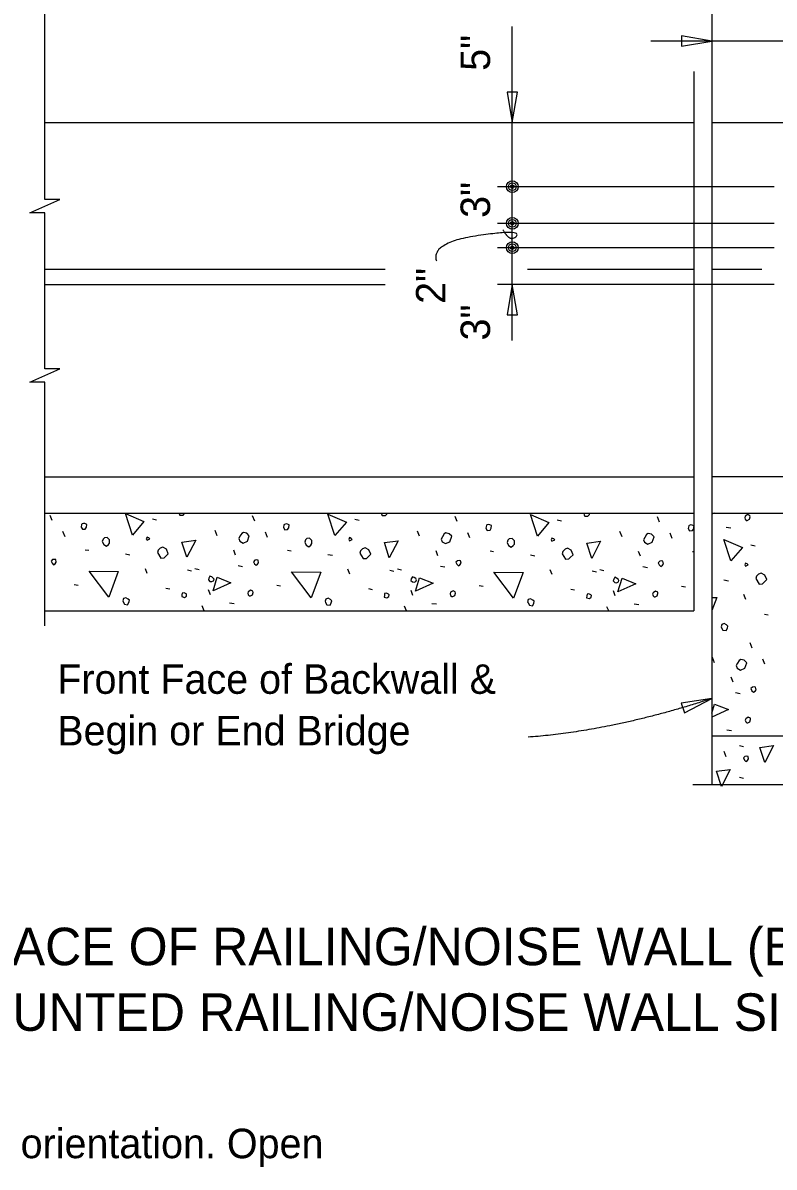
# Model space of a CAD drawing. Extents: x 120631.6 to 120706.2, y 120663.5 to 120716.4.
# Drawn here: x 120645.66 to 120650.79, y 120690.08 to 120697.89 of the extents above; entities that cross this region are included whole.
import ezdxf

# ---------------------------------------------------------------- set-up
doc = ezdxf.new("R2010")
doc.units = 0
for name, color, linetype in [('Dimension', 7, 'Continuous'), ('Miscellaneous', 7, 'Continuous'), ('TextStructures', 7, 'Continuous'), ('TrafBarrierConc', 7, 'Continuous')]:
    doc.layers.add(name, color=color, linetype=linetype)

msp = doc.modelspace()

# ---------------------------------------------------------------- linework, layer by layer
at = {"layer": 'Dimension'}
for p, q in [((120648.9987, 120695.7265), (120648.9987, 120697.8695)), ((120652.0739, 120697.7695), (120649.9443, 120697.7695)), ((120650.787, 120696.7752), (120648.8978, 120696.7752)), ((120650.787, 120696.5252), (120648.8978, 120696.5252)), ((120650.787, 120696.3586), (120648.8978, 120696.3586)), ((120650.787, 120696.1086), (120648.8978, 120696.1086))]:
    msp.add_line(p, q, dxfattribs=at)
for points in [[(120645.8063, 120697.2127), (120645.8063, 120699.4757), (120645.703, 120699.4757), (120645.8063, 120699.5207), (120645.9097, 120699.5657), (120645.8063, 120699.5657), (120645.8063, 120702.646)], [(120645.8063, 120696.2127), (120645.8063, 120696.597), (120645.703, 120696.597), (120645.8063, 120696.642), (120645.9097, 120696.687), (120645.8063, 120696.687), (120645.8063, 120697.2127)], [(120645.8063, 120693.7786), (120645.8063, 120695.4418), (120645.703, 120695.4418), (120645.8063, 120695.4868), (120645.9097, 120695.5318), (120645.8063, 120695.5318), (120645.8063, 120696.2127)], [(120651.6828, 120692.6914), (120650.9858, 120692.6914), (120650.9858, 120692.5751), (120650.8864, 120692.8001), (120650.8864, 120692.6914), (120650.2312, 120692.6914)]]:
    msp.add_lwpolyline(points, dxfattribs=at)
for points in [[(120650.362, 120697.7695), (120650.1537, 120697.8048), (120650.1537, 120697.7342)], [(120648.9987, 120697.2127), (120649.0339, 120697.421), (120648.9634, 120697.421)], [(120648.9987, 120696.1086), (120648.9634, 120695.9003), (120649.0339, 120695.9003)], [(120650.362, 120693.2821), (120650.1532, 120693.2502), (120650.1754, 120693.1832)]]:
    msp.add_lwpolyline(points, close=True, dxfattribs=at)
for centre, radius in [((120648.9994, 120696.7756), 0.0399), ((120648.9994, 120696.7756), 0.0262), ((120648.9994, 120696.7756), 0.0118), ((120648.9994, 120696.5256), 0.0399), ((120648.9994, 120696.5256), 0.0262), ((120648.9994, 120696.5256), 0.0118), ((120648.9994, 120696.3589), 0.0399), ((120648.9994, 120696.3589), 0.0262), ((120648.9994, 120696.3589), 0.0118)]:
    msp.add_circle(centre, radius, dxfattribs=at)
for points in [[(120648.9344, 120696.4819), (120648.9857, 120696.39), (120649.069, 120696.4866), (120648.4422, 120696.3928), (120648.4805, 120696.2684)], [(120650.362, 120693.2821), (120649.6982, 120693.0626), (120649.1068, 120693.0177)]]:
    msp.add_open_spline(points, degree=2, dxfattribs=at)
at = {"layer": 'Miscellaneous'}
for p, q in [((120645.8575, 120694.4966), (120645.8434, 120694.5319)), ((120646.5416, 120694.509), (120646.5699, 120694.5019)), ((120647.2399, 120694.4931), (120647.2257, 120694.5284)), ((120647.924, 120694.5054), (120647.9523, 120694.4983)), ((120648.6223, 120694.4895), (120648.6081, 120694.5249)), ((120649.3064, 120694.5019), (120649.3347, 120694.4949)), ((120650.0047, 120694.486), (120649.9905, 120694.5214)), ((120645.9441, 120694.3852), (120645.93, 120694.4206)), ((120646.9836, 120694.3923), (120646.9694, 120694.4277)), ((120647.3265, 120694.3817), (120647.3124, 120694.417)), ((120648.366, 120694.3888), (120648.3518, 120694.4241)), ((120648.7089, 120694.3781), (120648.6948, 120694.4135)), ((120649.7484, 120694.3852), (120649.7342, 120694.4206)), ((120650.0913, 120694.3746), (120650.0772, 120694.41)), ((120650.4607, 120694.4502), (120650.4926, 120694.4466)), ((120646.082, 120694.2968), (120646.1067, 120694.2933)), ((120650.6287, 120694.3317), (120650.657, 120694.3247)), ((120646.3578, 120694.2686), (120646.3878, 120694.2632)), ((120647.1091, 120694.2597), (120647.0967, 120694.2933)), ((120647.4644, 120694.2933), (120647.4891, 120694.2897)), ((120647.7402, 120694.265), (120647.7702, 120694.2597)), ((120648.4915, 120694.2562), (120648.4791, 120694.2897)), ((120648.8468, 120694.2897), (120648.8715, 120694.2863)), ((120649.1226, 120694.2615), (120649.1526, 120694.2562)), ((120649.8739, 120694.2527), (120649.8615, 120694.2863)), ((120650.2292, 120694.2863), (120650.2395, 120694.2848)), ((120646.5063, 120694.1342), (120646.4939, 120694.1678)), ((120646.7803, 120694.1607), (120646.8086, 120694.1537)), ((120646.8315, 120694.1695), (120646.8598, 120694.1625)), ((120647.1267, 120694.189), (120647.1568, 120694.1837)), ((120647.8887, 120694.1307), (120647.8763, 120694.1643)), ((120648.1627, 120694.1572), (120648.191, 120694.1501)), ((120648.2139, 120694.1661), (120648.2422, 120694.159)), ((120648.5091, 120694.1855), (120648.5392, 120694.1802)), ((120649.2711, 120694.1271), (120649.2587, 120694.1607)), ((120649.5451, 120694.1537), (120649.5734, 120694.1466)), ((120649.5963, 120694.1625), (120649.6246, 120694.1554)), ((120649.8915, 120694.1819), (120649.9216, 120694.1766)), ((120650.4448, 120694.0913), (120650.4749, 120694.086)), ((120646.0078, 120694.06), (120646.0343, 120694.0546)), ((120646.6336, 120694.0352), (120646.6601, 120694.0299)), ((120646.9376, 120693.9892), (120646.9252, 120694.0228)), ((120647.3902, 120694.0564), (120647.4167, 120694.0511)), ((120648.016, 120694.0317), (120648.0425, 120694.0264)), ((120648.32, 120693.9857), (120648.3076, 120694.0193)), ((120648.7726, 120694.0529), (120648.7991, 120694.0476)), ((120649.3984, 120694.0281), (120649.4249, 120694.0228)), ((120649.7024, 120693.9822), (120649.69, 120694.0158)), ((120650.155, 120694.0493), (120650.1815, 120694.0441)), ((120650.5933, 120693.957), (120650.5809, 120693.9906)), ((120646.8952, 120693.8796), (120646.8811, 120693.915)), ((120647.0666, 120693.9344), (120647.0985, 120693.9309)), ((120648.2763, 120693.8794), (120648.2635, 120693.9115)), ((120648.449, 120693.9309), (120648.4809, 120693.9274)), ((120649.6573, 120693.8794), (120649.6459, 120693.9079)), ((120649.8314, 120693.9274), (120649.8632, 120693.9239)), ((120650.7206, 120693.858), (120650.7471, 120693.8527)), ((120650.6375, 120693.6264), (120650.6234, 120693.6618)), ((120650.3812, 120693.5256), (120650.367, 120693.561)), ((120650.7241, 120693.515), (120650.71, 120693.5504)), ((120650.5067, 120693.3931), (120650.4943, 120693.4266)), ((120650.5244, 120693.3223), (120650.5544, 120693.317)), ((120650.4643, 120693.0678), (120650.4961, 120693.0643)), ((120650.4601, 120692.8837), (120650.446, 120692.919)), ((120650.5506, 120692.9603), (120650.5771, 120692.955)), ((120650.5506, 120692.7437), (120650.5771, 120692.7384))]:
    msp.add_line(p, q, dxfattribs=at)
for points in [[(120646.4055, 120694.3976), (120646.3578, 120694.5443), (120646.4833, 120694.4895), (120646.4055, 120694.3976)], [(120646.7237, 120694.5461), (120646.729, 120694.5337), (120646.7255, 120694.5372)], [(120646.729, 120694.5337), (120646.7502, 120694.5337), (120646.7609, 120694.5443), (120646.7604, 120694.5461)], [(120647.7879, 120694.3941), (120647.7402, 120694.5408), (120647.8657, 120694.486), (120647.7879, 120694.3941)], [(120648.1082, 120694.5461), (120648.1061, 120694.5426), (120648.1114, 120694.5302), (120648.1079, 120694.5337)], [(120648.1114, 120694.5302), (120648.1326, 120694.5302), (120648.1432, 120694.5408), (120648.1418, 120694.5461)], [(120649.1703, 120694.3905), (120649.1226, 120694.5372), (120649.2481, 120694.4825), (120649.1703, 120694.3905)], [(120649.4927, 120694.5461), (120649.4885, 120694.539), (120649.4938, 120694.5267), (120649.4903, 120694.5302)], [(120649.4938, 120694.5267), (120649.515, 120694.5267), (120649.5256, 120694.5372), (120649.5232, 120694.5461)], [(120650.3777, 120694.546), (120650.362, 120694.5389)], [(120650.5969, 120694.4979), (120650.6039, 120694.4979), (120650.6181, 120694.505), (120650.6234, 120694.5209), (120650.6216, 120694.5297), (120650.6075, 120694.5368), (120650.5898, 120694.5262), (120650.5862, 120694.5156), (120650.5898, 120694.505), (120650.5969, 120694.4979)], [(120646.0537, 120694.4524), (120646.0626, 120694.4365), (120646.082, 120694.4382), (120646.0909, 120694.4506), (120646.0926, 120694.4701), (120646.0802, 120694.4754), (120646.0714, 120694.4771), (120646.0608, 120694.4736), (120646.0573, 120694.4701), (120646.0537, 120694.4524)], [(120647.4361, 120694.4489), (120647.445, 120694.433), (120647.4644, 120694.4347), (120647.4732, 120694.4471), (120647.475, 120694.4666), (120647.4626, 120694.4718), (120647.4538, 120694.4736), (120647.4432, 120694.4701), (120647.4397, 120694.4666), (120647.4361, 120694.4489)], [(120648.8185, 120694.4453), (120648.8274, 120694.4294), (120648.8468, 120694.4312), (120648.8556, 120694.4436), (120648.8574, 120694.463), (120648.845, 120694.4683), (120648.8362, 120694.4701), (120648.8256, 120694.4666), (120648.8221, 120694.463), (120648.8185, 120694.4453)], [(120650.2395, 120694.4596), (120650.2274, 120694.4648), (120650.2186, 120694.4666), (120650.208, 120694.463), (120650.2044, 120694.4595), (120650.2009, 120694.4418)], [(120650.2009, 120694.4418), (120650.2098, 120694.4259), (120650.2292, 120694.4277), (120650.238, 120694.44), (120650.2395, 120694.4561)], [(120646.1987, 120694.3534), (120646.2093, 120694.3322), (120646.2269, 120694.3216), (120646.2411, 120694.3322), (120646.2482, 120694.3428), (120646.2482, 120694.364), (120646.2323, 120694.3799), (120646.2128, 120694.3781), (120646.204, 120694.3693), (120646.1987, 120694.3534)], [(120646.5045, 120694.3622), (120646.524, 120694.3711), (120646.5169, 120694.3781), (120646.5045, 120694.3834), (120646.4992, 120694.3711), (120646.5045, 120694.3622)], [(120647.1374, 120694.3552), (120647.1603, 120694.3428), (120647.1904, 120694.3552), (120647.2028, 120694.3923), (120647.1851, 120694.41), (120647.1621, 120694.4153), (120647.1515, 120694.4082), (120647.1391, 120694.3888), (120647.1303, 120694.3729), (120647.1374, 120694.3552)], [(120647.5811, 120694.3499), (120647.5917, 120694.3287), (120647.6093, 120694.318), (120647.6235, 120694.3287), (120647.6306, 120694.3393), (120647.6306, 120694.3605), (120647.6147, 120694.3764), (120647.5952, 120694.3746), (120647.5864, 120694.3658), (120647.5811, 120694.3499)], [(120647.8869, 120694.3587), (120647.9063, 120694.3676), (120647.8993, 120694.3746), (120647.8869, 120694.3799), (120647.8816, 120694.3676), (120647.8869, 120694.3587)], [(120648.5198, 120694.3516), (120648.5427, 120694.3393), (120648.5728, 120694.3516), (120648.5852, 120694.3888), (120648.5675, 120694.4065), (120648.5445, 120694.4117), (120648.5339, 120694.4047), (120648.5215, 120694.3852), (120648.5127, 120694.3693), (120648.5198, 120694.3516)], [(120648.9635, 120694.3464), (120648.9741, 120694.3251), (120648.9917, 120694.3145), (120649.0059, 120694.3251), (120649.013, 120694.3357), (120649.013, 120694.3569), (120648.9971, 120694.3729), (120648.9776, 120694.3711), (120648.9688, 120694.3622), (120648.9635, 120694.3464)], [(120649.2693, 120694.3552), (120649.2887, 120694.364), (120649.2817, 120694.3711), (120649.2693, 120694.3764), (120649.264, 120694.364), (120649.2693, 120694.3552)], [(120649.9022, 120694.3481), (120649.9251, 120694.3357), (120649.9552, 120694.3481), (120649.9676, 120694.3852), (120649.9499, 120694.4029), (120649.9269, 120694.4082), (120649.9163, 120694.4012), (120649.9039, 120694.3817), (120649.8951, 120694.3658), (120649.9022, 120694.3481)], [(120646.5752, 120694.2774), (120646.5982, 120694.2403), (120646.6212, 120694.242), (120646.63, 120694.2509), (120646.6494, 120694.2703), (120646.6371, 120694.3004), (120646.6124, 120694.3145), (120646.5947, 120694.3075), (120646.5805, 120694.2933), (120646.5752, 120694.2774)], [(120646.7767, 120694.2456), (120646.7431, 120694.3499), (120646.8368, 120694.3622), (120646.7767, 120694.2456)], [(120647.9576, 120694.2739), (120647.9806, 120694.2367), (120648.0036, 120694.2385), (120648.0124, 120694.2474), (120648.0318, 120694.2668), (120648.0195, 120694.2968), (120647.9948, 120694.311), (120647.9771, 120694.3039), (120647.9629, 120694.2897), (120647.9576, 120694.2739)], [(120648.1591, 120694.242), (120648.1255, 120694.3464), (120648.2192, 120694.3587), (120648.1591, 120694.242)], [(120649.34, 120694.2703), (120649.363, 120694.2332), (120649.386, 120694.235), (120649.3948, 120694.2438), (120649.4142, 120694.2632), (120649.4019, 120694.2933), (120649.3771, 120694.3075), (120649.3594, 120694.3004), (120649.3453, 120694.2863), (120649.34, 120694.2703)], [(120649.5415, 120694.2385), (120649.5079, 120694.3428), (120649.6016, 120694.3552), (120649.5415, 120694.2385)], [(120650.4926, 120694.2204), (120650.4448, 120694.3671), (120650.5703, 120694.3123), (120650.4926, 120694.2204)], [(120645.8557, 120694.2049), (120645.8663, 120694.1943), (120645.8769, 120694.2014), (120645.884, 120694.212), (120645.8805, 120694.2296), (120645.8716, 120694.2314), (120645.8593, 120694.2296), (120645.8487, 120694.2191), (120645.8557, 120694.2049)], [(120647.2381, 120694.2014), (120647.2487, 120694.1908), (120647.2593, 120694.1978), (120647.2664, 120694.2084), (120647.2629, 120694.2262), (120647.254, 120694.2279), (120647.2417, 120694.2262), (120647.2311, 120694.2155), (120647.2381, 120694.2014)], [(120648.6205, 120694.1978), (120648.6311, 120694.1872), (120648.6417, 120694.1943), (120648.6488, 120694.2049), (120648.6453, 120694.2226), (120648.6364, 120694.2244), (120648.6241, 120694.2226), (120648.6135, 120694.212), (120648.6205, 120694.1978)], [(120650.0029, 120694.1943), (120650.0135, 120694.1837), (120650.0241, 120694.1908), (120650.0312, 120694.2014), (120650.0277, 120694.2191), (120650.0188, 120694.2208), (120650.0065, 120694.2191), (120649.9959, 120694.2084), (120650.0029, 120694.1943)], [(120646.2429, 120693.9733), (120646.1085, 120694.1501), (120646.3083, 120694.1483), (120646.2429, 120693.9733)], [(120647.6253, 120693.9698), (120647.4909, 120694.1466), (120647.6907, 120694.1448), (120647.6253, 120693.9698)], [(120649.0077, 120693.9663), (120648.8733, 120694.143), (120649.0731, 120694.1413), (120649.0077, 120693.9663)], [(120650.5915, 120694.185), (120650.611, 120694.1939), (120650.6039, 120694.2009), (120650.5915, 120694.2062), (120650.5862, 120694.1939), (120650.5915, 120694.185)], [(120646.9341, 120694.0812), (120646.9464, 120694.0794), (120646.9588, 120694.0847), (120646.9624, 120694.0953), (120646.9571, 120694.1042), (120646.9464, 120694.1112), (120646.9341, 120694.1165), (120646.927, 120694.1024), (120646.9235, 120694.0918), (120646.9341, 120694.0812)], [(120646.9553, 120694.0175), (120646.9836, 120694.1094), (120647.0773, 120694.0724), (120646.9553, 120694.0175)], [(120648.3165, 120694.0776), (120648.3288, 120694.0759), (120648.3412, 120694.0812), (120648.3448, 120694.0918), (120648.3394, 120694.1006), (120648.3288, 120694.1077), (120648.3165, 120694.113), (120648.3094, 120694.0989), (120648.3059, 120694.0882), (120648.3165, 120694.0776)], [(120648.3377, 120694.014), (120648.366, 120694.1059), (120648.4597, 120694.0688), (120648.3377, 120694.014)], [(120649.6989, 120694.0741), (120649.7112, 120694.0724), (120649.7236, 120694.0776), (120649.7272, 120694.0882), (120649.7218, 120694.0971), (120649.7112, 120694.1042), (120649.6989, 120694.1094), (120649.6918, 120694.0953), (120649.6882, 120694.0847), (120649.6989, 120694.0741)], [(120649.7201, 120694.0105), (120649.7484, 120694.1024), (120649.8421, 120694.0653), (120649.7201, 120694.0105)], [(120650.6623, 120694.1002), (120650.6852, 120694.063), (120650.7082, 120694.0648), (120650.7171, 120694.0737), (120650.7365, 120694.0931), (120650.7241, 120694.1231), (120650.6994, 120694.1373), (120650.6817, 120694.1302), (120650.6676, 120694.1161), (120650.6623, 120694.1002)], [(120646.7414, 120693.9769), (120646.7609, 120693.9716), (120646.7732, 120693.9804), (120646.775, 120693.9928), (120646.7714, 120693.9963), (120646.7573, 120694.0034), (120646.7449, 120694.0016), (120646.7431, 120693.9892), (120646.7414, 120693.9769)], [(120647.2028, 120693.9822), (120647.2099, 120693.9822), (120647.224, 120693.9892), (120647.2293, 120694.0052), (120647.2275, 120694.014), (120647.2134, 120694.0211), (120647.1957, 120694.0105), (120647.1922, 120693.9999), (120647.1957, 120693.9892), (120647.2028, 120693.9822)], [(120648.1238, 120693.9733), (120648.1432, 120693.968), (120648.1556, 120693.9769), (120648.1574, 120693.9892), (120648.1538, 120693.9928), (120648.1397, 120693.9999), (120648.1273, 120693.9981), (120648.1255, 120693.9857), (120648.1238, 120693.9733)], [(120648.5852, 120693.9787), (120648.5923, 120693.9787), (120648.6064, 120693.9857), (120648.6117, 120694.0016), (120648.6099, 120694.0105), (120648.5958, 120694.0175), (120648.5781, 120694.0069), (120648.5746, 120693.9963), (120648.5781, 120693.9857), (120648.5852, 120693.9787)], [(120649.5062, 120693.9698), (120649.5256, 120693.9645), (120649.538, 120693.9733), (120649.5398, 120693.9857), (120649.5362, 120693.9892), (120649.5221, 120693.9963), (120649.5097, 120693.9945), (120649.5079, 120693.9822), (120649.5062, 120693.9698)], [(120649.9676, 120693.9751), (120649.9747, 120693.9751), (120649.9888, 120693.9822), (120649.9941, 120693.9981), (120649.9923, 120694.0069), (120649.9781, 120694.014), (120649.9605, 120694.0034), (120649.9569, 120693.9928), (120649.9605, 120693.9822), (120649.9676, 120693.9751)], [(120646.3419, 120693.9415), (120646.3507, 120693.9256), (120646.3719, 120693.9221), (120646.3807, 120693.938), (120646.3843, 120693.9521), (120646.3754, 120693.9609), (120646.3596, 120693.9698), (120646.3437, 120693.9645), (120646.3384, 120693.9486), (120646.3419, 120693.9415)], [(120647.7243, 120693.938), (120647.7331, 120693.9221), (120647.7543, 120693.9186), (120647.7631, 120693.9344), (120647.7667, 120693.9486), (120647.7578, 120693.9574), (120647.7419, 120693.9663), (120647.726, 120693.9609), (120647.7207, 120693.9451), (120647.7243, 120693.938)], [(120649.1066, 120693.9344), (120649.1155, 120693.9186), (120649.1367, 120693.915), (120649.1455, 120693.9309), (120649.1491, 120693.9451), (120649.1402, 120693.9539), (120649.1243, 120693.9627), (120649.1084, 120693.9574), (120649.1031, 120693.9415), (120649.1066, 120693.9344)], [(120650.362, 120693.9714), (120650.3953, 120693.9711), (120650.362, 120693.882)], [(120650.4289, 120693.7643), (120650.4378, 120693.7484), (120650.459, 120693.7448), (120650.4678, 120693.7608), (120650.4713, 120693.7749), (120650.4625, 120693.7837), (120650.4466, 120693.7926), (120650.4307, 120693.7873), (120650.4254, 120693.7714), (120650.4289, 120693.7643)], [(120650.535, 120693.4885), (120650.558, 120693.4761), (120650.588, 120693.4885), (120650.6004, 120693.5256), (120650.5827, 120693.5433), (120650.5597, 120693.5486), (120650.5491, 120693.5416), (120650.5367, 120693.5221), (120650.5279, 120693.5062), (120650.535, 120693.4885)], [(120650.6357, 120693.3347), (120650.6463, 120693.3241), (120650.657, 120693.3312), (120650.664, 120693.3418), (120650.6605, 120693.3595), (120650.6517, 120693.3612), (120650.6393, 120693.3595), (120650.6287, 120693.3489), (120650.6357, 120693.3347)], [(120650.362, 120693.1805), (120650.3812, 120693.2428), (120650.4749, 120693.2057), (120650.362, 120693.155)], [(120650.6004, 120693.1155), (120650.6075, 120693.1155), (120650.6216, 120693.1226), (120650.6269, 120693.1385), (120650.6251, 120693.1473), (120650.611, 120693.1544), (120650.5933, 120693.1438), (120650.5898, 120693.1332), (120650.5933, 120693.1226), (120650.6004, 120693.1155)], [(120650.7236, 120692.844), (120650.69, 120692.9483), (120650.7837, 120692.9607), (120650.7236, 120692.844)], [(120650.5843, 120692.8619), (120650.5949, 120692.8513), (120650.6055, 120692.8584), (120650.6125, 120692.869), (120650.609, 120692.8867), (120650.6002, 120692.8884), (120650.5878, 120692.8867), (120650.5772, 120692.876), (120650.5843, 120692.8619)], [(120650.427, 120692.6807), (120650.3934, 120692.785), (120650.4871, 120692.7974), (120650.427, 120692.6807)]]:
    msp.add_lwpolyline(points, dxfattribs=at)
at = {"layer": 'TrafBarrierConc'}
for p, q in [((120650.362, 120702.4835), (120650.362, 120692.6914)), ((120650.2395, 120697.561), (120650.2395, 120693.8794)), ((120645.8063, 120697.2127), (120650.2395, 120697.2127)), ((120650.362, 120697.2127), (120653.9962, 120697.2127)), ((120645.8063, 120696.2127), (120648.1317, 120696.2127)), ((120649.1022, 120696.2127), (120650.2395, 120696.2127)), ((120650.362, 120696.2127), (120650.7029, 120696.2127)), ((120645.8063, 120696.1085), (120648.1317, 120696.1085)), ((120645.8063, 120694.796), (120650.2395, 120694.796)), ((120650.362, 120694.7961), (120653.9962, 120694.7961)), ((120645.8063, 120694.546), (120650.2395, 120694.546)), ((120650.362, 120694.5461), (120653.9962, 120694.5461)), ((120645.8063, 120693.8794), (120650.2395, 120693.8794)), ((120651.582, 120693.0237), (120650.362, 120693.0237))]:
    msp.add_line(p, q, dxfattribs=at)

# ---------------------------------------------------------------- texts
at = {"layer": 'Dimension'}
for s, height, p in [('Front Face of Backwall &', 0.2016, (120645.8914, 120693.3136)), ('Begin or End Bridge', 0.2016, (120645.8914, 120692.9616)), ('ELEVATION OF INSIDE FACE OF RAILING/NOISE WALL (BRIDGE MOUNTED RAILING/NOISE WALL SHOWN, ', 0.256001, (120641.547, 120691.4611)), ('WALL OR FOOTING MOUNTED RAILING/NOISE WALL SIMILAR) (Reinforcing Steel not shown for clarity)', 0.256001, (120641.7426, 120691.0131)), ('* On Bridges see Superstructure and Approach Slab Sheets for actual dimensions and joint orientation. Open ', 0.2016004, (120634.6865, 120690.1437))]:
    msp.add_text(s, height=height, dxfattribs=at).set_placement(p)
at = {"layer": 'TextStructures'}
for s, p in [('5"', (120648.8473, 120697.5663)), ('3"', (120648.8473, 120696.5624)), ('2"', (120648.5428, 120695.9754)), ('3"', (120648.8473, 120695.7257))]:
    msp.add_text(s, height=0.2016, rotation=90, dxfattribs=at).set_placement(p)

doc.saveas('drawing.dxf')
